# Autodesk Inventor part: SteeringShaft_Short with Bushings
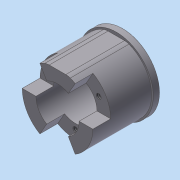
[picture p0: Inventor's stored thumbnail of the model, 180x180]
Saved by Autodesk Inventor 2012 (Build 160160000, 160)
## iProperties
Created: 2010-12
Part Number: SteeringShaft_Short with Bushings
Document SubType Name: Modeling
Designer: Alex
Density: 2.71 g/cm^3
Material: Aluminum-6061
Mass: 56.844 g
Surface Area: 77.866 cm^2
Volume: 20.9757 cm^3
Author: Alex
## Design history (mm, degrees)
sketch "Sketch1"
  geometry: C1 r 19.05 at (0, 0); 1 further point
  constraints: 1 centre point
  dimensions: "d0" = 38.1 diameter of C1
extrude "Extrusion1" new body sketch "Sketch1" distance "d1" = 33.40735; taper "d2" = 0 deg
workplane "Work Plane1"
sketch "Sketch2"
  geometry: C1 r 18.161 at (0, 0); C2 r 19.05 at (0, 0); 1 further point
  constraints: 2 centre point
  dimensions: "d4" = 36.322 diameter of C1; "d5" = 38.1 diameter of C2
extrude "Extrusion2" cut sketch "Sketch2" distance "d6" = 50.8; taper "d7" = 0 deg
sketch "Sketch3"
  geometry: C1 r 9.525 at (0, 0)
  constraints: 1 centre point
  dimensions: "d8" = 19.05 diameter of C1
extrude "Extrusion3" cut sketch "Sketch3" distance "d9" = 38.1; taper "d10" = 0 deg
sketch "Sketch4"
  geometry: L1 (-25.44, 0)-(0, 0); L2 (0, 0)-(0, -13.843); L3 (0, 0)-(11.988, 6.921); L4 (0, 0)-(-11.988, 6.921); C1 r 9.525 at (0, 0) reference; C2 r 18.161 at (0, 0) reference
  constraints: 8 end point, 1 horizontal, 1 vertical, 10 other
  dimensions: "d59" = 13.843 distance of L1.end L2.end; "d62" = 360 deg dimension on C1.centre L2.end (derived)
hole "#6-32 Threaded Holes" sketch "Sketch4" at (0, -13.843), (-11.988, 6.921), (11.988, 6.921) diameter "d16" = 2.6416; stored, may be unused: countersink angle "d20" = 82 deg, drill point angle "d22" = 118 deg; dims "d17" = 19.05, "d18" = 7.62, "d19" = 7.9375, "d21" = 25.4
sketch "Sketch5"
  geometry: C1 r 9.525 at (0, 0) reference; C2 r 11.113 at (0, 0)
  constraints: 1 centre point
  dimensions: "d23" = 22.225 diameter of C2
extrude "Extrusion4" cut sketch "Sketch5" distance "d24" = 7.874; taper "d25" = 0 deg
sketch "Sketch6"
  geometry: L1 (-9.525, 30.067)-(9.525, 30.067); L2 (9.525, 30.067)-(9.525, 17.367); L3 (9.525, 17.367)-(-9.525, 17.367); L4 (-9.525, 17.367)-(-9.525, 30.067); C1 r 9.525 at (0, 0) reference
  constraints: 8 end point, 2 parallel, 1 horizontal, 1 perpendicular
  dimensions: "d26" = 12.7 distance between parallel lines of L3 L1; "d64" = 17.36725 distance from line of C1.centre L3
extrude "Extrusion5" cut sketch "Sketch6" stored distance "d28" = 30.9626; taper "d29" = 0 deg
fillet "Fillet1" dims "d30" = 6.35
sketch "Sketch8"
  geometry: C1 r 19.05 at (0, 0) reference; C2 r 12.294 at (0, 0)
  constraints: 1 centre point, 1 coincident
  dimensions: "d39" = 24.5872 diameter of C2
extrude "Extrusion7" cut sketch "Sketch8" distance "d40" = 1.524; taper "d41" = 0 deg
sketch "Sketch9"
  geometry: C1 r 9.525 at (0, 0) reference; C2 r 11.113 at (0, 0)
  constraints: 1 centre point, 1 coincident
  dimensions: "d42" = 22.225 diameter of C2
extrude "Extrusion8" cut sketch "Sketch9" distance "d43" = 3.175; taper "d44" = 0 deg
sketch "Sketch10"
  geometry: C1 r 9.525 at (0, 0) reference; C2 r 11.113 at (0, 0)
  constraints: 1 centre point, 1 coincident
  dimensions: "d45" = 22.225 diameter of C2
extrude "Extrusion9" cut sketch "Sketch10" stored distance "d46" = 3.6068; taper "d47" = 0 deg
sketch "Sketch11"
  geometry: L1 (0, 0)-(0, -18.161); L2 (0, 0)-(-9.081, -15.728); L3 (0, 0)-(9.081, -15.728); L4 (0, 0)-(18.161, 0); L5 (0, 0)-(9.08, 15.728); L6 (0, 0)-(-9.081, 15.728); L7 (0, 0)-(-18.161, 0); A1 r 11.112 centre (0, 0) between (11.113, 0) and (11.113, 0) reference; A2 r 18.161 centre (0, 0) between (-6.545, 16.941) and (6.545, 16.941) reference
  constraints: 14 end point, 3 point on circle, 16 other
  dimensions: "d48" = 30 deg angle of L1 L2; "d49" = 30 deg angle of L3 L1; "d52" = 360 deg dimension on A1.centre L2.end (derived)
extrude "Extrusion10" cut sketch "Sketch11" distance "d54" = 9.1694; taper "d55" = 0 deg
pattern_circular "Circular Pattern1" dims angle "d57" = 360 deg
body "Solid1"
other parameters: "d3" = 3.175
